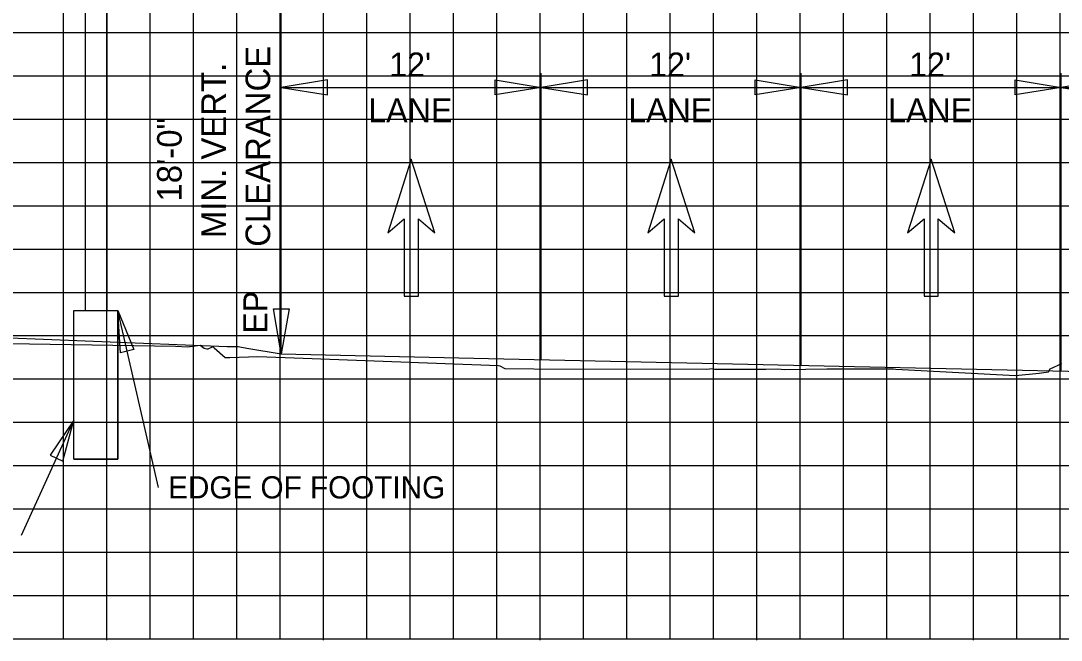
# Model space of a CAD drawing. Extents: x 2193008 to 2198143, y 1236112 to 1237864.
# Drawn here: x 2194733.71 to 2194781.74, y 1237163.05 to 1237191.64 of the extents above; entities that cross this region are included whole.
import ezdxf

# ---------------------------------------------------------------- set-up
doc = ezdxf.new("R2010")
doc.units = 0
for name, color, linetype in [('3', 7, 'Continuous'), ('60', 7, 'Continuous'), ('CL-CNST', 7, 'Continuous'), ('GSDIMS', 7, 'Continuous'), ('Level 28', 7, 'Continuous'), ('Level 55', 7, 'Continuous'), ('Level 62', 7, 'Continuous'), ('M-ROADS', 7, 'Continuous'), ('V7Level1', 7, 'Continuous')]:
    doc.layers.add(name, color=color, linetype=linetype)

msp = doc.modelspace()

# ---------------------------------------------------------------- linework, layer by layer
at = {"layer": '3'}
for p, q in [((2194736.688, 1237202.797), (2194736.688, 1237178.261)), ((2194737.688, 1237202.797), (2194737.688, 1237178.261)), ((2194745.739, 1237176.26), (2194745.739, 1237194.26)), ((2194757.739, 1237175.996), (2194757.739, 1237189.229)), ((2194769.739, 1237175.732), (2194769.739, 1237189.229)), ((2194781.739, 1237175.468), (2194781.739, 1237189.229)), ((2194736.163, 1237178.261), (2194738.188, 1237178.261)), ((2194736.163, 1237171.409), (2194736.163, 1237178.261)), ((2194738.188, 1237171.409), (2194738.188, 1237178.261)), ((2194740.076, 1237170.1), (2194738.188, 1237178.261)), ((2194733.738, 1237167.898), (2194736.163, 1237173.2)), ((2194736.163, 1237171.409), (2194738.188, 1237171.409))]:
    msp.add_line(p, q, dxfattribs=at)
at = {"layer": '60'}
for p, q in [((2194697.688, 1237163.106), (2194827.688, 1237163.106)), ((2194737.688, 1237163.046), (2194737.688, 1237163.106)), ((2194747.688, 1237163.046), (2194747.688, 1237163.106)), ((2194757.688, 1237163.046), (2194757.688, 1237163.106)), ((2194767.688, 1237163.046), (2194767.688, 1237163.106)), ((2194777.688, 1237163.046), (2194777.688, 1237163.106))]:
    msp.add_line(p, q, dxfattribs=at)
at = {"layer": 'CL-CNST'}
msp.add_lwpolyline([(2194697.688, 1237175.995), (2194709.741, 1237176.26), (2194710.142, 1237176.328), (2194711.741, 1237176.6), (2194711.841, 1237176.6), (2194712.241, 1237176.6), (2194715.381, 1237176.726), (2194727.74, 1237177.22), (2194730.881, 1237177.095), (2194743.239, 1237176.6), (2194743.639, 1237176.6), (2194743.739, 1237176.6), (2194744.14, 1237176.532), (2194745.739, 1237176.26), (2194755.304, 1237176.05), (2194793.33, 1237175.213)], dxfattribs=at)
at = {"layer": 'GSDIMS'}
for p, q in [((2194745.739, 1237188.567), (2194757.739, 1237188.567)), ((2194757.739, 1237188.567), (2194769.739, 1237188.567)), ((2194769.739, 1237188.567), (2194781.739, 1237188.567)), ((2194781.739, 1237188.567), (2194793.739, 1237188.567))]:
    msp.add_line(p, q, dxfattribs=at)
for points in [[(2194745.739, 1237188.567), (2194747.867, 1237188.22), (2194747.867, 1237188.914)], [(2194757.739, 1237188.567), (2194755.611, 1237188.22), (2194755.611, 1237188.914)], [(2194757.739, 1237188.567), (2194759.867, 1237188.22), (2194759.867, 1237188.914)], [(2194769.739, 1237188.567), (2194767.611, 1237188.22), (2194767.611, 1237188.914)], [(2194769.739, 1237188.567), (2194771.867, 1237188.22), (2194771.867, 1237188.914)], [(2194781.739, 1237188.567), (2194779.611, 1237188.22), (2194779.611, 1237188.914)], [(2194781.739, 1237188.567), (2194783.867, 1237188.22), (2194783.867, 1237188.914)], [(2194745.739, 1237176.26), (2194745.384, 1237178.343), (2194746.094, 1237178.343)], [(2194738.188, 1237178.261), (2194738.933, 1237176.46), (2194738.309, 1237176.316)], [(2194736.163, 1237173.2), (2194735.072, 1237171.585), (2194735.655, 1237171.319)]]:
    msp.add_lwpolyline(points, close=True, dxfattribs=at)
at = {"layer": 'Level 28'}
for p, q in [((2194751.739, 1237185.257), (2194750.65, 1237181.859)), ((2194752.828, 1237181.859), (2194751.739, 1237185.257)), ((2194763.739, 1237185.257), (2194762.65, 1237181.859)), ((2194764.828, 1237181.859), (2194763.739, 1237185.257)), ((2194775.739, 1237185.257), (2194774.65, 1237181.859)), ((2194776.828, 1237181.859), (2194775.739, 1237185.257)), ((2194750.65, 1237181.859), (2194751.412, 1237182.499)), ((2194751.412, 1237182.499), (2194751.412, 1237178.927)), ((2194752.066, 1237178.927), (2194752.066, 1237182.499)), ((2194752.066, 1237182.499), (2194752.828, 1237181.859)), ((2194762.65, 1237181.859), (2194763.412, 1237182.499)), ((2194763.412, 1237182.499), (2194763.412, 1237178.927)), ((2194764.066, 1237178.927), (2194764.066, 1237182.499)), ((2194764.066, 1237182.499), (2194764.828, 1237181.859)), ((2194774.65, 1237181.859), (2194775.412, 1237182.499)), ((2194775.412, 1237182.499), (2194775.412, 1237178.927)), ((2194776.066, 1237178.927), (2194776.066, 1237182.499)), ((2194776.066, 1237182.499), (2194776.828, 1237181.859)), ((2194751.412, 1237178.927), (2194752.066, 1237178.927)), ((2194763.412, 1237178.927), (2194764.066, 1237178.927)), ((2194775.412, 1237178.927), (2194776.066, 1237178.927))]:
    msp.add_line(p, q, dxfattribs=at)
at = {"layer": 'Level 62'}
for p, q in [((2194735.688, 1237163.106), (2194735.688, 1237223.106)), ((2194737.688, 1237163.106), (2194737.688, 1237223.106)), ((2194739.688, 1237163.106), (2194739.688, 1237223.106)), ((2194741.688, 1237163.106), (2194741.688, 1237223.106)), ((2194743.688, 1237163.106), (2194743.688, 1237223.106)), ((2194745.688, 1237163.106), (2194745.688, 1237223.106)), ((2194747.688, 1237163.106), (2194747.688, 1237223.106)), ((2194749.688, 1237163.106), (2194749.688, 1237223.106)), ((2194751.688, 1237163.106), (2194751.688, 1237223.106)), ((2194753.688, 1237163.106), (2194753.688, 1237223.106)), ((2194755.688, 1237163.106), (2194755.688, 1237223.106)), ((2194757.688, 1237163.106), (2194757.688, 1237223.106)), ((2194759.688, 1237163.106), (2194759.688, 1237223.106)), ((2194761.688, 1237163.106), (2194761.688, 1237223.106)), ((2194763.688, 1237163.106), (2194763.688, 1237223.106)), ((2194765.688, 1237163.106), (2194765.688, 1237223.106)), ((2194767.688, 1237163.106), (2194767.688, 1237223.106)), ((2194769.688, 1237163.106), (2194769.688, 1237223.106)), ((2194771.688, 1237163.106), (2194771.688, 1237223.106)), ((2194773.688, 1237163.106), (2194773.688, 1237223.106)), ((2194775.688, 1237163.106), (2194775.688, 1237223.106)), ((2194777.688, 1237163.106), (2194777.688, 1237223.106)), ((2194779.688, 1237163.106), (2194779.688, 1237223.106)), ((2194781.688, 1237163.106), (2194781.688, 1237223.106)), ((2194697.688, 1237191.106), (2194827.688, 1237191.106)), ((2194697.688, 1237189.106), (2194827.688, 1237189.106)), ((2194697.688, 1237187.106), (2194827.688, 1237187.106)), ((2194697.688, 1237185.106), (2194827.688, 1237185.106)), ((2194697.688, 1237183.106), (2194827.688, 1237183.106)), ((2194697.688, 1237181.106), (2194827.688, 1237181.106)), ((2194697.688, 1237179.106), (2194827.688, 1237179.106)), ((2194697.688, 1237177.106), (2194827.688, 1237177.106)), ((2194697.688, 1237175.106), (2194827.688, 1237175.106)), ((2194697.688, 1237173.106), (2194827.688, 1237173.106)), ((2194697.688, 1237171.106), (2194827.688, 1237171.106)), ((2194697.688, 1237169.106), (2194827.688, 1237169.106)), ((2194697.688, 1237167.106), (2194827.688, 1237167.106)), ((2194697.688, 1237165.106), (2194827.688, 1237165.106)), ((2194697.688, 1237163.106), (2194827.688, 1237163.106))]:
    msp.add_line(p, q, dxfattribs=at)
at = {"layer": 'M-ROADS'}
msp.add_lwpolyline([(2194716.763, 1237177.01), (2194740.861, 1237176.616), (2194741.424, 1237176.583), (2194741.497, 1237176.611), (2194741.529, 1237176.604), (2194741.994, 1237176.674), (2194742.178, 1237176.522), (2194742.293, 1237176.496), (2194742.354, 1237176.496), (2194742.564, 1237176.595), (2194742.572, 1237176.604), (2194742.573, 1237176.599), (2194742.642, 1237176.541), (2194743.148, 1237176.099), (2194743.362, 1237176.104), (2194744.65, 1237176.144), (2194746.749, 1237176.067), (2194755.769, 1237175.728), (2194755.819, 1237175.711), (2194756.061, 1237175.588), (2194757.398, 1237175.576), (2194765.358, 1237175.561), (2194765.665, 1237175.59), (2194765.739, 1237175.562), (2194766.192, 1237175.562), (2194768.105, 1237175.557), (2194768.639, 1237175.57), (2194768.976, 1237175.548), (2194770.916, 1237175.573), (2194772.681, 1237175.576), (2194773.997, 1237175.574), (2194774.108, 1237175.564), (2194779.632, 1237175.27), (2194780.72, 1237175.374), (2194781.159, 1237175.436), (2194781.223, 1237175.568), (2194781.763, 1237175.827)], dxfattribs=at)
at = {"layer": 'V7Level1'}
msp.add_lwpolyline([(2194738.188, 1237171.409), (2194736.163, 1237171.409), (2194736.163, 1237178.261), (2194738.188, 1237178.261)], close=True, dxfattribs=at)

# ---------------------------------------------------------------- texts
at = {"layer": 'Level 55'}
for s, height, p in [('CLEARANCE', 1.1346, (2194745.224, 1237181.21)), ('MIN. VERT.', 1.1346, (2194743.182, 1237181.61)), ('18\'-0"', 1.1346, (2194741.139, 1237183.298)), ('EP', 1.1105, (2194745.099, 1237177.192))]:
    msp.add_text(s, height=height, rotation=90, dxfattribs=at).set_placement(p)
for s, height, p in [("12'", 1.1105, (2194750.718, 1237189.067)), ("12'", 1.1105, (2194762.718, 1237189.067)), ("12'", 1.1105, (2194774.718, 1237189.067)), ('LANE', 1.1105, (2194749.753, 1237186.956)), ('LANE', 1.1105, (2194761.753, 1237186.956)), ('LANE', 1.1105, (2194773.753, 1237186.956)), ('EDGE OF FOOTING', 1.02464, (2194740.514, 1237169.591))]:
    msp.add_text(s, height=height, dxfattribs=at).set_placement(p)

doc.saveas('drawing.dxf')
